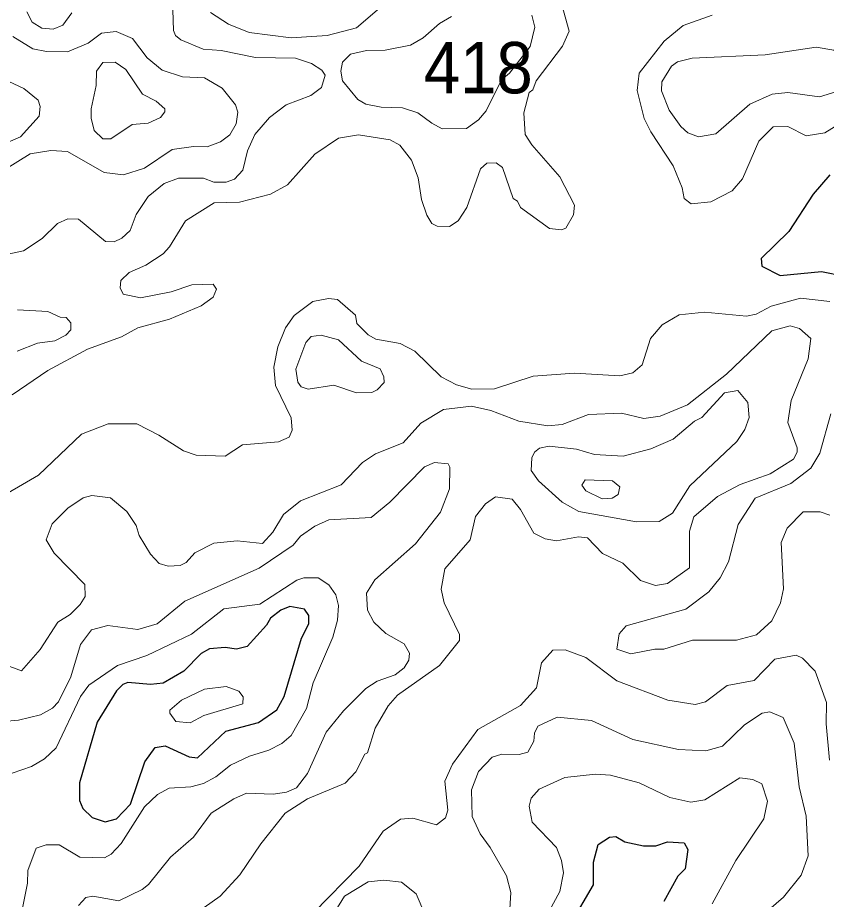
# Model space of a CAD drawing. Extents: x 763.2 to 816.8, y 7896.5 to 7952.7.
# Drawn here: x 772.72 to 775.238, y 7903.274 to 7906.02 of the extents above; entities that cross this region are included whole.
import ezdxf

# ---------------------------------------------------------------- set-up
doc = ezdxf.new("R2010")
doc.units = 0
doc.header["$LTSCALE"] = 0.064
doc.layers.add('1', color=7, linetype='Continuous', lineweight=25)
doc.layers.add('2', color=7, linetype='Continuous', lineweight=13)
doc.layers.add('21', color=7, linetype='Continuous')

msp = doc.modelspace()

# ---------------------------------------------------------------- linework, layer by layer
at = {"layer": '1'}
for points in [[(775.2488, 7905.5308), (775.1972, 7905.4703), (775.1207, 7905.3546), (775.0352, 7905.2703), (775.0373, 7905.2466), (775.0946, 7905.2167), (775.223, 7905.2298), (775.2945, 7905.2152)], [(774.4411, 7903.196), (774.5125, 7903.3192), (774.5132, 7903.39), (774.5274, 7903.4442), (774.5627, 7903.4673), (774.5829, 7903.4695), (774.6107, 7903.4532), (774.6683, 7903.4402), (774.707, 7903.4403), (774.7439, 7903.4532), (774.7955, 7903.4497), (774.807, 7903.4285), (774.7989, 7903.3688), (774.7756, 7903.3457), (774.7317, 7903.2668)]]:
    msp.add_lwpolyline(points, dxfattribs=at)
msp.add_lwpolyline([(773.6036, 7904.0878), (773.6265, 7904.1318), (773.6262, 7904.1579), (773.6131, 7904.178), (773.5673, 7904.1858), (773.5395, 7904.1742), (773.5071, 7904.1495), (773.4952, 7904.1283), (773.4348, 7904.0616), (773.4015, 7904.0532), (773.3659, 7904.058), (773.3176, 7904.0544), (773.2913, 7904.0395), (773.2377, 7903.9846), (773.1735, 7903.9469), (773.1341, 7903.9432), (773.0636, 7903.9494), (773.0476, 7903.9435), (773.0281, 7903.9234), (772.9681, 7903.8256), (772.9126, 7903.6365), (772.9125, 7903.5814), (772.9227, 7903.5564), (772.9519, 7903.529), (772.9928, 7903.5147), (773.0273, 7903.5242), (773.071, 7903.5704), (773.1165, 7903.7018), (773.1486, 7903.7469), (773.1793, 7903.752), (773.2543, 7903.718), (773.2803, 7903.7149), (773.3687, 7903.7979), (773.4704, 7903.8246), (773.5272, 7903.8645), (773.5502, 7903.906)], close=True, dxfattribs=at)
at = {"layer": '2'}
for points in [[(772.1929, 7906.2184), (772.2905, 7906.0201), (772.3204, 7905.9734), (772.35, 7905.9076), (772.3813, 7905.8791), (772.4283, 7905.8869), (772.477, 7905.9265), (772.5213, 7905.9446), (772.5782, 7905.9397), (772.6162, 7905.9116), (772.6771, 7905.8283), (772.7395, 7905.7993), (772.7839, 7905.7633), (772.7906, 7905.7432), (772.7872, 7905.7132), (772.7286, 7905.649), (772.6396, 7905.6111), (772.531, 7905.5339)], [(772.7485, 7906.0381), (772.765, 7906.0068), (772.7949, 7905.9872), (772.8305, 7905.9842), (772.8612, 7905.9971), (772.8892, 7906.0352)], [(773.2031, 7906.0443), (773.205, 7905.98), (773.212, 7905.9646), (773.2283, 7905.9513), (773.2976, 7905.9217), (773.3542, 7905.9182), (773.4605, 7905.8964), (773.5855, 7905.8939), (773.6348, 7905.8776), (773.6671, 7905.8569), (773.6779, 7905.8415), (773.6657, 7905.8027), (773.6324, 7905.7775), (773.5566, 7905.749), (773.504, 7905.7097), (773.4587, 7905.6564), (773.4355, 7905.6056), (773.4216, 7905.5456)], [(773.8611, 7906.0621), (773.7753, 7905.9883), (773.6841, 7905.9644), (773.5716, 7905.9579), (773.4409, 7905.9745), (773.3765, 7906.0004), (773.32, 7906.0368)], [(773.6454, 7905.5947), (773.7189, 7905.6453), (773.7808, 7905.6554), (773.88, 7905.6395), (773.9104, 7905.6231), (773.9465, 7905.5768), (773.9672, 7905.5214), (773.9772, 7905.454), (773.9936, 7905.4047), (774.0095, 7905.3789), (774.0258, 7905.3712), (774.0647, 7905.3694), (774.0919, 7905.3874), (774.1182, 7905.4294), (774.161, 7905.5491), (774.1808, 7905.5672), (774.2104, 7905.5682), (774.2301, 7905.5533), (774.263, 7905.4572), (774.2761, 7905.4483), (774.2861, 7905.4293), (774.3761, 7905.3637), (774.4137, 7905.3597), (774.4269, 7905.3645), (774.4509, 7905.4065), (774.4536, 7905.4363), (774.4086, 7905.5245), (774.3208, 7905.6244), (774.2999, 7905.6566), (774.2964, 7905.7243), (774.3128, 7905.7868), (774.324, 7905.7957), (774.334, 7905.8231), (774.4163, 7905.9312), (774.4371, 7905.9786), (774.4147, 7906.0607)], [(774.0705, 7906.0244), (774.0338, 7906.0026), (773.9826, 7905.957), (773.9431, 7905.9344), (773.8647, 7905.9186), (773.8058, 7905.9183), (773.7561, 7905.907), (773.731, 7905.8821), (773.726, 7905.8537), (773.7314, 7905.8231), (773.7789, 7905.7653), (773.8044, 7905.7507), (773.8524, 7905.741), (773.9187, 7905.7394), (773.9664, 7905.7236), (774.0101, 7905.6919), (774.0418, 7905.6742), (774.1176, 7905.6753), (774.1554, 7905.7022), (774.1786, 7905.7297), (774.2268, 7905.8268), (774.2515, 7905.8476), (774.316, 7905.9306), (774.3305, 7905.9906), (774.3206, 7906.0285)], [(774.883, 7906.0281), (774.7925, 7905.9955), (774.7327, 7905.9474), (774.6551, 7905.847), (774.6491, 7905.7935), (774.6709, 7905.7065), (774.6918, 7905.6644), (774.7612, 7905.5586), (774.7888, 7905.4902), (774.7958, 7905.4573), (774.8168, 7905.4407), (774.8779, 7905.4468), (774.9447, 7905.4807), (774.977, 7905.5183), (775.0282, 7905.636), (775.072, 7905.6799), (775.1176, 7905.6815), (775.1752, 7905.6523), (775.2338, 7905.6614), (775.2986, 7905.7016)], [(772.6822, 7905.5486), (772.7592, 7905.5966), (772.8236, 7905.6061), (772.8755, 7905.603), (772.9899, 7905.5378), (773.0498, 7905.5307), (773.1148, 7905.5513), (773.201, 7905.6091), (773.268, 7905.6193), (773.3105, 7905.6181), (773.352, 7905.6339), (773.3802, 7905.6552), (773.4001, 7905.6898), (773.4053, 7905.7257), (773.3988, 7905.7484), (773.3573, 7905.8004), (773.3015, 7905.8324), (773.2338, 7905.8365), (773.17, 7905.857), (773.1228, 7905.8953), (773.0772, 7905.9556), (773.0263, 7905.9777), (772.9816, 7905.9725), (772.9396, 7905.9412), (772.8756, 7905.9135), (772.8095, 7905.9149), (772.7672, 7905.9237), (772.7047, 7905.9616)], [(773.2423, 7905.387), (773.3321, 7905.4435), (773.4109, 7905.4455), (773.5078, 7905.4701), (773.5603, 7905.4998), (773.6454, 7905.5947)], [(773.4216, 7905.5456), (773.3949, 7905.5172), (773.3697, 7905.5077), (773.3305, 7905.5076), (773.2989, 7905.5206), (773.2207, 7905.5205)], [(773.2207, 7905.5205), (773.1764, 7905.5032), (773.1259, 7905.4632), (773.0891, 7905.4073), (773.0703, 7905.3569), (773.0443, 7905.3337), (773.0201, 7905.3223), (772.9939, 7905.3234), (772.9095, 7905.3922), (772.8762, 7905.3941), (772.8438, 7905.3796), (772.7965, 7905.3326), (772.7387, 7905.2942), (772.6751, 7905.2808)], [(772.7026, 7904.8457), (772.8138, 7904.9208), (772.937, 7904.9881), (773.0432, 7905.0259), (773.0938, 7905.0541), (773.193, 7905.0808), (773.2916, 7905.1221), (773.3292, 7905.1492), (773.3393, 7905.175), (773.3284, 7905.1905), (773.2625, 7905.1885), (773.1983, 7905.1658), (773.1026, 7905.1478), (773.0488, 7905.1594), (773.0391, 7905.1784), (773.041, 7905.2015), (773.0673, 7905.2264), (773.1193, 7905.2497), (773.1733, 7905.2848), (773.1929, 7905.3065), (773.2423, 7905.387)], [(775.2493, 7905.1361), (775.1573, 7905.146), (775.0659, 7905.1214), (775.0192, 7905.0969), (774.989, 7905.0907), (774.8589, 7905.1033), (774.7795, 7905.0949), (774.7268, 7905.0637), (774.6905, 7905.0204), (774.6648, 7904.9388), (774.6354, 7904.9138), (774.5952, 7904.9046), (774.4539, 7904.9126), (774.3253, 7904.9031), (774.2046, 7904.8641), (774.1343, 7904.8631), (774.0864, 7904.8763), (774.0389, 7904.9013), (773.9564, 7904.9811), (773.9109, 7905.0048), (773.8349, 7905.0188), (773.8116, 7905.032), (773.7762, 7905.0676), (773.7722, 7905.0936), (773.7164, 7905.1421), (773.6882, 7905.1459), (773.6392, 7905.1366), (773.5809, 7905.0928), (773.5536, 7905.0537), (773.5304, 7904.9946), (773.5174, 7904.9314), (773.5233, 7904.8744), (773.5719, 7904.7737), (773.5747, 7904.735)], [(772.7191, 7905.1099), (772.8137, 7905.1048), (772.8527, 7905.0872), (772.8711, 7905.0865), (772.8856, 7905.0694), (772.886, 7905.0474), (772.8696, 7905.031), (772.836, 7905.0137), (772.7819, 7905.0064), (772.7184, 7904.9817)], [(772.6794, 7904.0048), (772.7324, 7903.986), (772.7897, 7904.0518), (772.8456, 7904.1373), (772.8838, 7904.161), (772.9151, 7904.1924), (772.9302, 7904.2176), (772.9291, 7904.2546), (772.8338, 7904.3517), (772.8092, 7904.3933), (772.8279, 7904.4435), (772.8762, 7904.4919), (772.9239, 7904.5247), (772.9508, 7904.5314), (773.0091, 7904.5247), (773.0601, 7904.4815), (773.0893, 7904.4384), (773.0981, 7904.407), (773.1337, 7904.3493), (773.1602, 7904.3196), (773.1891, 7904.3112), (773.2256, 7904.314), (773.2445, 7904.3231), (773.272, 7904.353), (773.3305, 7904.3833), (773.403, 7904.3901), (773.4825, 7904.3821), (773.5148, 7904.4177), (773.5475, 7904.4726), (773.601, 7904.5149), (773.7274, 7904.5645), (773.7934, 7904.6347), (773.834, 7904.6618), (773.9207, 7904.6955), (773.9754, 7904.7575), (774.0461, 7904.7993), (774.1333, 7904.8104), (774.1936, 7904.7961), (774.2804, 7904.763), (774.371, 7904.7484), (774.4151, 7904.7534), (774.4975, 7904.7842), (774.6003, 7904.7878), (774.6701, 7904.7715), (774.7206, 7904.7787), (774.8061, 7904.8145), (774.9272, 7904.9094), (775.0682, 7905.0447), (775.1251, 7905.0603), (775.1549, 7905.0524), (775.1899, 7905.0208), (775.1819, 7904.957), (775.1289, 7904.8275), (775.118, 7904.7589), (775.1474, 7904.6803), (775.1473, 7904.6669), (775.136, 7904.6454), (775.0633, 7904.5994), (774.9693, 7904.5656), (774.8996, 7904.5288), (774.8255, 7904.465), (774.8123, 7904.4202), (774.8119, 7904.3069), (774.7437, 7904.2574), (774.7061, 7904.2518), (774.6598, 7904.2667), (774.6044, 7904.3213), (774.5415, 7904.3516), (774.4948, 7904.3996), (774.4663, 7904.4031), (774.3973, 7904.3902), (774.363, 7904.3963), (774.327, 7904.414), (774.2853, 7904.4883), (774.2593, 7904.5201), (774.2076, 7904.528), (774.1767, 7904.5056), (774.1452, 7904.4668), (774.1294, 7904.3939), (774.0502, 7904.3031), (774.0382, 7904.2401), (774.0482, 7904.1972), (774.0955, 7904.0991), (774.0955, 7904.0803), (774.0331, 7904.0023), (773.9029, 7903.9094), (773.8739, 7903.8767), (773.8327, 7903.8066)], [(775.2485, 7904.4706), (775.219, 7904.4805), (775.1656, 7904.4807), (775.1164, 7904.4305), (775.0975, 7904.3857), (775.1046, 7904.2414), (775.0948, 7904.1979), (775.0679, 7904.1415), (775.0202, 7904.0973), (774.9583, 7904.0812), (774.8212, 7904.0814), (774.7323, 7904.0533), (774.7039, 7904.0534), (774.6291, 7904.0383), (774.5858, 7904.0535), (774.5925, 7904.1009), (774.6151, 7904.1254), (774.8003, 7904.1772), (774.8718, 7904.2312), (774.9077, 7904.2757), (774.9333, 7904.3253), (774.9634, 7904.441), (775.0166, 7904.5234), (775.1277, 7904.5694), (775.1901, 7904.6167), (775.2173, 7904.6636), (775.2523, 7904.7865)], [(773.2755, 7904.6572), (773.236, 7904.6711), (773.1595, 7904.7202), (773.0913, 7904.7546), (773.0014, 7904.7546), (772.9192, 7904.7233), (772.7854, 7904.5948), (772.6394, 7904.5107)], [(773.5747, 7904.735), (773.5652, 7904.7135), (773.5325, 7904.699), (773.42, 7904.6893), (773.3657, 7904.6539), (773.2755, 7904.6572)], [(772.9094, 7903.2542), (772.9321, 7903.279), (772.9543, 7903.2837), (773.0355, 7903.2694), (773.1078, 7903.3039), (773.1275, 7903.3203), (773.1962, 7903.4051), (773.2675, 7903.4673), (773.3221, 7903.5425), (773.3936, 7903.5871), (773.4326, 7903.6043), (773.5153, 7903.6014), (773.5572, 7903.608), (773.5882, 7903.6214), (773.6224, 7903.666), (773.6807, 7903.7949), (773.7346, 7903.8613), (773.8038, 7903.9306), (773.8392, 7903.9529), (773.8953, 7903.9736), (773.9237, 7903.9951), (773.9376, 7904.0188), (773.9404, 7904.0406), (773.9237, 7904.0702), (773.8662, 7904.1022), (773.8291, 7904.1376), (773.8097, 7904.1748), (773.8064, 7904.2276), (773.8319, 7904.2691), (773.9587, 7904.3813), (774.0368, 7904.4797), (774.0642, 7904.5528), (774.066, 7904.6203), (774.0602, 7904.6299), (774.0183, 7904.6348), (773.9873, 7904.6215), (773.8792, 7904.5105), (773.8204, 7904.463), (773.6887, 7904.4557), (773.6453, 7904.436), (773.6011, 7904.405), (773.5782, 7904.3774), (773.4725, 7904.3054), (773.2404, 7904.2023), (773.1549, 7904.1319), (773.0938, 7904.1141), (773.0013, 7904.1272), (772.9499, 7904.113), (772.9156, 7904.0672), (772.8858, 7903.9671), (772.8468, 7903.8895), (772.8282, 7903.8693), (772.7914, 7903.8481), (772.7224, 7903.8314), (772.6764, 7903.828)], [(772.7029, 7903.6665), (772.7631, 7903.6879), (772.8041, 7903.711), (772.8404, 7903.7453), (772.9161, 7903.9057), (772.942, 7903.9413), (773.0313, 7904.0024), (773.1219, 7904.0337), (773.2612, 7904.0996), (773.3623, 7904.1792), (773.4744, 7904.193), (773.5895, 7904.2684), (773.6115, 7904.2752), (773.6557, 7904.275), (773.6885, 7904.2532), (773.7107, 7904.2221), (773.7191, 7904.1894), (773.7159, 7904.1429), (773.7016, 7904.0907), (773.6405, 7903.948), (773.6199, 7903.8679), (773.5713, 7903.7837), (773.5421, 7903.7587), (773.5021, 7903.7383), (773.4416, 7903.7195), (773.3824, 7903.6914), (773.3366, 7903.6551), (773.2983, 7903.6347), (773.2597, 7903.6246), (773.1922, 7903.6197), (773.1556, 7903.6007), (773.1153, 7903.5621), (773.0428, 7903.4472), (773.0114, 7903.4144), (772.9904, 7903.4026), (772.9134, 7903.4046), (772.8491, 7903.4434), (772.8086, 7903.4435), (772.7777, 7903.4332), (772.7516, 7903.3636), (772.7512, 7903.3241), (772.7352, 7903.246)], [(773.6416, 7903.232), (773.7838, 7903.3766), (773.8582, 7903.4866), (773.9123, 7903.5239), (773.951, 7903.5271), (774.0246, 7903.5059), (774.0524, 7903.5277), (774.0593, 7903.5518), (774.0498, 7903.6422), (774.0741, 7903.6952), (774.1526, 7903.8025), (774.2862, 7903.8774), (774.3357, 7903.933), (774.3507, 7904.0109), (774.3863, 7904.0499), (774.425, 7904.0513), (774.4894, 7904.0271), (774.5853, 7903.9546), (774.744, 7903.8944), (774.8295, 7903.8807), (774.8613, 7903.8891), (774.9287, 7903.9402), (775.0133, 7903.9557), (775.0774, 7904.0218), (775.1438, 7904.0348), (775.1639, 7904.0252), (775.2035, 7903.985), (775.239, 7903.887), (775.2379, 7903.8205), (775.2474, 7903.7072)], [(775.0293, 7903.2149), (775.1042, 7903.2803), (775.1598, 7903.3492), (775.1819, 7903.4089), (775.175, 7903.533), (775.1537, 7903.624), (775.1376, 7903.7599), (775.104, 7903.8399), (775.062, 7903.8574), (775.0383, 7903.8539), (774.9835, 7903.8172), (774.9145, 7903.7513), (774.8624, 7903.7359), (774.7775, 7903.7407), (774.636, 7903.7719), (774.5072, 7903.831), (774.4004, 7903.841), (774.3392, 7903.8129), (774.329, 7903.7911), (774.3268, 7903.7663), (774.3081, 7903.7321), (774.2814, 7903.7248), (774.2279, 7903.7256), (774.1976, 7903.717), (774.155, 7903.6716), (774.1334, 7903.6153), (774.135, 7903.532), (774.1602, 7903.4774), (774.1917, 7903.4354), (774.2417, 7903.3473), (774.2559, 7903.2951), (774.2514, 7903.2267)], [(773.8327, 7903.8066), (773.8097, 7903.7301), (773.8013, 7903.7255), (773.773, 7903.6714), (773.7399, 7903.6352), (773.6223, 7903.5864)], [(774.3422, 7903.1755), (774.4083, 7903.2985), (774.4193, 7903.3563), (774.4131, 7903.3943), (774.3978, 7903.4351), (774.3221, 7903.514), (774.3126, 7903.5645), (774.3188, 7903.5886), (774.3434, 7903.617), (774.4234, 7903.6536), (774.5196, 7903.6635), (774.5656, 7903.6603), (774.6553, 7903.6366), (774.7512, 7903.5909), (774.8161, 7903.5766), (774.8596, 7903.5838), (774.9684, 7903.6519), (775.0093, 7903.6472), (775.0375, 7903.6334), (775.0553, 7903.5794), (775.043, 7903.5248), (774.9564, 7903.3952), (774.8821, 7903.2601)], [(773.6223, 7903.5864), (773.5534, 7903.5419), (773.4777, 7903.4467), (773.4119, 7903.3498), (773.3507, 7903.2835), (773.3008, 7903.2483)], [(774.0175, 7903.1572), (773.9611, 7903.2914), (773.9157, 7903.3275), (773.8604, 7903.3332), (773.8114, 7903.3287), (773.7373, 7903.2833), (773.6688, 7903.1728)]]:
    msp.add_lwpolyline(points, dxfattribs=at)
for points in [[(775.0001, 7905.7507), (775.0692, 7905.7821), (775.1178, 7905.7869), (775.2171, 7905.7739), (775.2809, 7905.793), (775.3108, 7905.8225), (775.305, 7905.8805), (775.2613, 7905.9186), (775.206, 7905.9284), (775.0477, 7905.9048), (774.8207, 7905.8937), (774.7748, 7905.8831), (774.7554, 7905.8697), (774.7258, 7905.8205), (774.725, 7905.7926), (774.7485, 7905.7322), (774.785, 7905.6812), (774.8069, 7905.6616), (774.8399, 7905.649), (774.8936, 7905.6586)], [(773.1089, 7905.7818), (773.0572, 7905.859), (773.0241, 7905.882), (772.9854, 7905.8806), (772.9652, 7905.8538), (772.9649, 7905.8093), (772.9486, 7905.7359), (772.9486, 7905.7076), (772.9586, 7905.6689), (772.9852, 7905.6426), (773.0105, 7905.6424), (773.0761, 7905.6879), (773.1267, 7905.6919), (773.1645, 7905.7093), (773.1781, 7905.7265), (773.178, 7905.7362), (773.1509, 7905.7603)], [(773.7046, 7904.8753), (773.7749, 7904.8517), (773.8227, 7904.8529), (773.8398, 7904.8606), (773.8616, 7904.8842), (773.8603, 7904.9018), (773.8484, 7904.9262), (773.7904, 7904.9507), (773.7186, 7905.0162), (773.665, 7905.0308), (773.634, 7905.0275), (773.617, 7905.0082), (773.5866, 7904.9256), (773.5926, 7904.8853), (773.6027, 7904.8703), (773.625, 7904.8634)], [(774.9839, 7904.7375), (774.998, 7904.7744), (774.9931, 7904.8217), (774.9623, 7904.8593), (774.9204, 7904.8513), (774.8501, 7904.7747), (774.8275, 7904.7632), (774.7611, 7904.7073), (774.6914, 7904.6769), (774.6059, 7904.6544), (774.5163, 7904.6596), (774.4603, 7904.6766), (774.3754, 7904.6855), (774.345, 7904.6789), (774.3295, 7904.6665), (774.3211, 7904.6487), (774.3192, 7904.6096), (774.342, 7904.5775), (774.415, 7904.5112), (774.4671, 7904.4821), (774.6472, 7904.4494), (774.7177, 7904.4508), (774.7589, 7904.4768), (774.8129, 7904.5617), (774.959, 7904.6996)], [(774.5724, 7904.577), (774.5955, 7904.559), (774.59, 7904.5344), (774.5715, 7904.5231), (774.54, 7904.5216), (774.4888, 7904.5461), (774.4769, 7904.5637), (774.4875, 7904.5805)], [(773.4088, 7903.9223), (773.3694, 7903.9363), (773.3013, 7903.9284), (773.2299, 7903.8945), (773.1939, 7903.8627), (773.1935, 7903.8533), (773.2124, 7903.8274), (773.2573, 7903.8233), (773.3002, 7903.846), (773.4212, 7903.8827), (773.4218, 7903.9042)]]:
    msp.add_lwpolyline(points, close=True, dxfattribs=at)

# ---------------------------------------------------------------- texts
at = {"layer": '21', "width": 0.95}
msp.add_text('418', height=0.16, dxfattribs=at).set_placement((773.9847, 7905.7846))

doc.saveas('drawing.dxf')
